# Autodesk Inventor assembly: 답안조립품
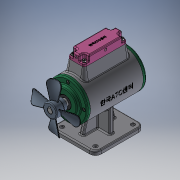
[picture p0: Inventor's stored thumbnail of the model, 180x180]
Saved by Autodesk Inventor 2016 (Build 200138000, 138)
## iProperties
Created: 2021-02
Part Number: 답안조립품
Document SubType Name: Assembly
Designer: Windows7
Mass: 2275.08 g
Surface Area: 2702.33 cm^2
Volume: 961.308 cm^3
Density: 2.36665 g/cm^3
Author: Windows7
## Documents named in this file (19)
- C:\Users\Windows7\Desktop\610204v1007\답안조립품.iam
- C:\Users\Windows7\Desktop\610204v1007\본체.ipt
- C:\Users\Windows7\Desktop\610204v1007\축.ipt
- C:\Users\Windows7\Desktop\610204v1007\키 5 x 5 x 26.ipt
- C:\Users\Windows7\Desktop\610204v1007\베어링 6203.ipt
- C:\Users\Windows7\Desktop\610204v1007\앞커버.ipt
- C:\Users\Windows7\Desktop\610204v1007\오일실 17 30 8.ipt
- C:\Users\Windows7\Desktop\610204v1007\볼트 M4 x 12.ipt
- C:\Users\Windows7\Desktop\610204v1007\팬날개.ipt
- 팬날개.ipt
- C:\Users\Windows7\Desktop\610204v1007\멈춤나사 M4 x 8.ipt
- C:\Users\Windows7\Desktop\610204v1007\뒤커버.ipt
- C:\Users\Windows7\Desktop\610204v1007\슬라이드.ipt
- C:\Users\Windows7\Desktop\610204v1007\부시.ipt
- C:\Users\Windows7\Desktop\610204v1007\헤더커버.ipt
- C:\Users\Windows7\Desktop\610204v1007\볼트 M4 x 16.ipt
- C:\Users\Windows7\Desktop\610204v1007\가변스프링1.ipt
- C:\Users\Windows7\Desktop\610204v1007\가변스프링2.ipt
- C:\Users\Windows7\Desktop\610204v1007\가변스프링3.ipt
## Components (4 placed, 4 different names)
1. 헤더커버:1
2. 가변스프링1:1
3. 가변스프링2:1
4. 가변스프링3:1
